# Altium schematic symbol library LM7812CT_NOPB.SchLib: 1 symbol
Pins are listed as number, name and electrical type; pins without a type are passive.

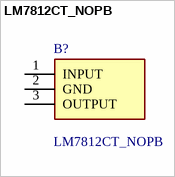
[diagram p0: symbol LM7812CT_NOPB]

## LM7812CT_NOPB
designator B?
Texas Instruments LM7812CT/NOPB Positive Voltage Regulator, 1A, 12 V 3-Pin, TO-220; Geometry.Height: 4.7mm
footprint TO254P470X1028X1955-3P
pins: 1 INPUT, 2 GND, 3 OUTPUT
